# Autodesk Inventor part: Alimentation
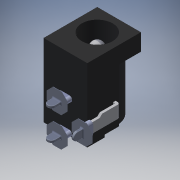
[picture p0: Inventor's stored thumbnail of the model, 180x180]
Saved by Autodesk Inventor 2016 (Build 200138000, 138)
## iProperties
Created: 2018-03
Part Number: Alimentation
Material: Générique
Document SubType Name: Modeling
Designer: Bruno
Density: 1 g/cm^3
Appearance: Par défaut
Author: Bruno
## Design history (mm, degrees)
feature "Composite1"
body "Srf1"
